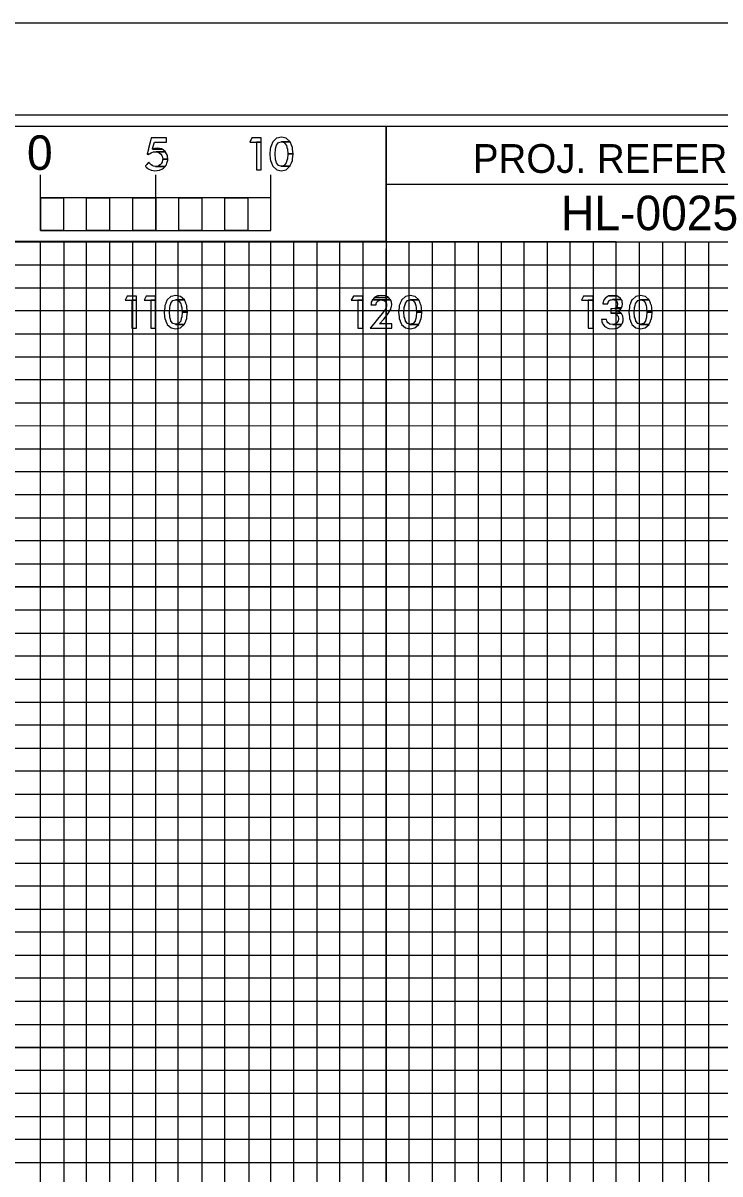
# Model space of a CAD drawing. Extents: x -13 to 323, y -5 to 1431.
# Drawn here: x 264.2 to 294.5, y 604.5 to 654.5 of the extents above; entities that cross this region are included whole.
import ezdxf

# ---------------------------------------------------------------- set-up
doc = ezdxf.new("R2010")
doc.units = 0
for name, color, linetype in [('Prop XS Bar Scale Labels', 7, 'Continuous'), ('Prop XS Offset Labels', 7, 'Continuous'), ('Prop XS Project Number', 7, 'Continuous'), ('Sheet Cross Section CELL', 7, 'Continuous'), ('Sheet Cross Section Grid Major CELL', 7, 'Continuous'), ('Sheet Cross Section Grid Middle CELL', 7, 'Continuous'), ('Sheet Cross Section Grid Minor 1 CELL', 7, 'Continuous'), ('Sheet Cross Section Grid Minor 2 CELL', 7, 'Continuous'), ('Sheet Cross Section Scale CELL', 7, 'Continuous'), ('Sheet Cutting Line CELL', 7, 'Continuous'), ('Sheet DOT Grid CELL', 7, 'Continuous'), ('Sheet Plot Border Inside CELL', 7, 'Continuous'), ('Sheet Plot Border Outside CELL', 7, 'Continuous')]:
    doc.layers.add(name, color=color, linetype=linetype)

msp = doc.modelspace()

# ---------------------------------------------------------------- linework, layer by layer
at = {"layer": 'Prop XS Bar Scale Labels'}
for points in [[(269.63, 648.81), (269.627, 648.798), (269.698, 648.798), (269.711, 648.81), (269.727, 648.824), (269.798, 648.867), (269.83, 648.877), (269.9, 648.899), (270.014, 648.905), (270.422, 648.905), (270.414, 648.92), (270.28, 649.015), (269.858, 649.015), (269.861, 649.028), (269.861, 649.028), (269.866, 649.048), (269.941, 649.326), (270.466, 649.326), (270.466, 649.511), (269.803, 649.511), (269.757, 649.326), (269.689, 649.048), (269.684, 649.028), (269.681, 649.015), (269.658, 648.92), (269.654, 648.905), (269.652, 648.899), (269.647, 648.877), (269.644, 648.867), (269.634, 648.824)], [(274.174, 649.511), (274.085, 649.329), (274.583, 649.329), (274.583, 649.511)], [(275.258, 648.125), (275.457, 648.084), (275.652, 648.125), (275.663, 648.127), (275.828, 648.279), (275.454, 648.279), (275.445, 648.281), (275.44, 648.283), (275.335, 648.312), (275.248, 648.425), (275.248, 648.426), (275.248, 648.426), (275.22, 648.527), (275.22, 648.529), (275.2, 648.602), (275.198, 648.606), (275.181, 648.809), (275.181, 648.811), (275.181, 648.813), (275.198, 649.015), (275.219, 649.092), (275.22, 649.094), (275.246, 649.192), (275.247, 649.195), (275.335, 649.31), (275.448, 649.339), (275.452, 649.34), (275.462, 649.343), (275.832, 649.343), (275.669, 649.492), (275.66, 649.494), (275.46, 649.538), (275.46, 649.538), (275.252, 649.494), (275.25, 649.492), (275.088, 649.343), (275.085, 649.34), (275.084, 649.339), (275.072, 649.31), (275.025, 649.195), (275.024, 649.192), (274.983, 649.094), (274.983, 649.092), (274.975, 649.015), (274.954, 648.813), (274.953, 648.811), (274.954, 648.809), (274.974, 648.606), (274.974, 648.602), (274.982, 648.529), (274.982, 648.527), (275.023, 648.426), (275.024, 648.425), (275.07, 648.312), (275.082, 648.283), (275.082, 648.281), (275.085, 648.279), (275.255, 648.127)], [(269.895, 649.028), (269.858, 649.015), (270.28, 649.015), (270.262, 649.028), (270.164, 649.048), (269.953, 649.048)], [(270.091, 649.062), (269.953, 649.048), (270.164, 649.048), (270.091, 649.062)], [(274.374, 649.329), (274.374, 648.12), (274.583, 648.12), (274.583, 649.329)], [(275.719, 649.015), (275.735, 648.813), (275.962, 648.813), (275.942, 649.015), (275.935, 649.092), (275.934, 649.094), (275.934, 649.094), (275.895, 649.192), (275.895, 649.192), (275.893, 649.195), (275.848, 649.31), (275.847, 649.31), (275.835, 649.339), (275.835, 649.34), (275.832, 649.343), (275.462, 649.343), (275.472, 649.34), (275.475, 649.339), (275.582, 649.31), (275.669, 649.195), (275.672, 649.192), (275.698, 649.094), (275.698, 649.092)], [(269.627, 648.798), (269.685, 648.786), (269.698, 648.798)], [(270.103, 648.288), (269.996, 648.269), (270.408, 648.269), (270.423, 648.288), (270.424, 648.289), (270.425, 648.29), (270.425, 648.29), (270.462, 648.336), (270.471, 648.347), (270.473, 648.353), (270.487, 648.405), (270.502, 648.46), (270.525, 648.544), (270.521, 648.591), (270.308, 648.591), (270.3, 648.544), (270.286, 648.46), (270.25, 648.405), (270.217, 648.353), (270.207, 648.347), (270.19, 648.336), (270.116, 648.29), (270.108, 648.289)], [(270.286, 648.711), (270.308, 648.591), (270.521, 648.591), (270.51, 648.711), (270.51, 648.711), (270.507, 648.751), (270.487, 648.786), (270.481, 648.798), (270.475, 648.81), (270.467, 648.824), (270.443, 648.867), (270.438, 648.877), (270.426, 648.899), (270.422, 648.905), (270.014, 648.905), (270.041, 648.899), (270.132, 648.877), (270.146, 648.867), (270.206, 648.824), (270.227, 648.81), (270.234, 648.798), (270.241, 648.786), (270.262, 648.751)], [(275.465, 648.281), (275.454, 648.279), (275.828, 648.279), (275.831, 648.281), (275.833, 648.283), (275.845, 648.312), (275.892, 648.425), (275.892, 648.426), (275.934, 648.527), (275.935, 648.529), (275.942, 648.602), (275.942, 648.606), (275.962, 648.809), (275.963, 648.811), (275.962, 648.813), (275.735, 648.813), (275.735, 648.811), (275.735, 648.809), (275.719, 648.606), (275.718, 648.602), (275.699, 648.529), (275.698, 648.527), (275.671, 648.426), (275.67, 648.425), (275.582, 648.312), (275.47, 648.283)], [(269.829, 648.103), (269.965, 648.084), (270.163, 648.103), (270.171, 648.107), (270.294, 648.167), (270.294, 648.167), (270.344, 648.191), (270.388, 648.245), (270.408, 648.269), (269.996, 648.269), (269.887, 648.288), (269.885, 648.289), (269.882, 648.29), (269.799, 648.336), (269.789, 648.347), (269.783, 648.353), (269.783, 648.353), (269.733, 648.405), (269.7, 648.455), (269.7, 648.455), (269.655, 648.405), (269.608, 648.353), (269.602, 648.347), (269.593, 648.336), (269.551, 648.29), (269.55, 648.289), (269.551, 648.288), (269.566, 648.269), (269.585, 648.245), (269.649, 648.191), (269.677, 648.167), (269.801, 648.107)]]:
    msp.add_lwpolyline(points, close=True, dxfattribs=at)
at = {"layer": 'Prop XS Offset Labels'}
for points in [[(268.76, 642.641), (268.671, 642.459), (269.17, 642.459), (269.17, 642.641)], [(269.587, 642.641), (269.498, 642.459), (269.997, 642.459), (269.997, 642.641)], [(270.672, 641.255), (270.871, 641.214), (271.066, 641.255), (271.077, 641.257), (271.242, 641.409), (270.868, 641.409), (270.858, 641.411), (270.853, 641.413), (270.749, 641.442), (270.662, 641.555), (270.661, 641.556), (270.661, 641.556), (270.634, 641.657), (270.633, 641.659), (270.613, 641.732), (270.612, 641.736), (270.594, 641.939), (270.594, 641.941), (270.595, 641.943), (270.612, 642.145), (270.633, 642.222), (270.633, 642.224), (270.66, 642.322), (270.661, 642.325), (270.749, 642.44), (270.862, 642.469), (270.865, 642.47), (270.876, 642.473), (271.246, 642.473), (271.082, 642.622), (271.074, 642.624), (270.873, 642.668), (270.873, 642.668), (270.665, 642.624), (270.663, 642.622), (270.502, 642.473), (270.499, 642.47), (270.498, 642.469), (270.486, 642.44), (270.439, 642.325), (270.437, 642.322), (270.397, 642.224), (270.397, 642.222), (270.389, 642.145), (270.367, 641.943), (270.367, 641.941), (270.367, 641.939), (270.387, 641.736), (270.388, 641.732), (270.395, 641.659), (270.396, 641.657), (270.437, 641.556), (270.437, 641.555), (270.483, 641.442), (270.495, 641.413), (270.496, 641.411), (270.499, 641.409), (270.669, 641.257)], [(278.581, 642.641), (278.492, 642.459), (278.99, 642.459), (278.99, 642.641)], [(279.507, 642.583), (279.41, 642.479), (280.197, 642.479), (280.108, 642.583)], [(279.512, 642.585), (279.507, 642.583), (280.108, 642.583), (280.106, 642.585), (279.974, 642.645), (279.958, 642.652), (279.794, 642.668), (279.794, 642.668), (279.685, 642.652), (279.637, 642.645)], [(280.851, 641.255), (281.051, 641.214), (281.245, 641.255), (281.256, 641.257), (281.422, 641.409), (281.048, 641.409), (281.038, 641.411), (281.033, 641.413), (280.928, 641.442), (280.841, 641.555), (280.841, 641.556), (280.841, 641.556), (280.813, 641.657), (280.813, 641.659), (280.793, 641.732), (280.792, 641.736), (280.774, 641.939), (280.774, 641.941), (280.774, 641.943), (280.792, 642.145), (280.812, 642.222), (280.813, 642.224), (280.839, 642.322), (280.84, 642.325), (280.928, 642.44), (281.041, 642.469), (281.045, 642.47), (281.055, 642.473), (281.425, 642.473), (281.262, 642.622), (281.254, 642.624), (281.053, 642.668), (281.053, 642.668), (280.845, 642.624), (280.843, 642.622), (280.681, 642.473), (280.678, 642.47), (280.678, 642.469), (280.665, 642.44), (280.618, 642.325), (280.617, 642.322), (280.577, 642.224), (280.576, 642.222), (280.568, 642.145), (280.547, 641.943), (280.547, 641.941), (280.547, 641.939), (280.567, 641.736), (280.567, 641.732), (280.575, 641.659), (280.575, 641.657), (280.616, 641.556), (280.617, 641.555), (280.663, 641.442), (280.675, 641.413), (280.676, 641.411), (280.679, 641.409), (280.848, 641.257)], [(288.581, 642.641), (288.492, 642.459), (288.99, 642.459), (288.99, 642.641)], [(289.42, 642.315), (289.418, 642.297), (289.626, 642.297), (289.627, 642.315), (289.639, 642.365), (289.64, 642.372), (289.641, 642.373), (289.683, 642.433), (289.688, 642.436), (289.696, 642.44), (289.748, 642.47), (289.785, 642.476), (289.795, 642.478), (289.835, 642.485), (290.217, 642.485), (290.165, 642.561), (290.129, 642.582), (290.128, 642.582), (290.022, 642.644), (289.982, 642.65), (289.69, 642.65), (289.678, 642.644), (289.553, 642.582), (289.536, 642.561), (289.471, 642.485), (289.466, 642.478), (289.465, 642.476), (289.463, 642.47), (289.452, 642.44), (289.45, 642.436), (289.449, 642.433), (289.428, 642.373), (289.427, 642.372), (289.425, 642.365)], [(289.853, 642.668), (289.69, 642.65), (289.982, 642.65)], [(290.851, 641.255), (291.051, 641.214), (291.245, 641.255), (291.256, 641.257), (291.422, 641.409), (291.048, 641.409), (291.038, 641.411), (291.033, 641.413), (290.928, 641.442), (290.841, 641.555), (290.841, 641.556), (290.841, 641.556), (290.813, 641.657), (290.813, 641.659), (290.793, 641.732), (290.792, 641.736), (290.774, 641.939), (290.774, 641.941), (290.774, 641.943), (290.792, 642.145), (290.812, 642.222), (290.813, 642.224), (290.839, 642.322), (290.84, 642.325), (290.928, 642.44), (291.041, 642.469), (291.045, 642.47), (291.055, 642.473), (291.425, 642.473), (291.262, 642.622), (291.254, 642.624), (291.053, 642.668), (291.053, 642.668), (290.845, 642.624), (290.843, 642.622), (290.681, 642.473), (290.678, 642.47), (290.678, 642.469), (290.665, 642.44), (290.618, 642.325), (290.617, 642.322), (290.577, 642.224), (290.576, 642.222), (290.568, 642.145), (290.547, 641.943), (290.547, 641.941), (290.547, 641.939), (290.567, 641.736), (290.567, 641.732), (290.575, 641.659), (290.575, 641.657), (290.616, 641.556), (290.617, 641.555), (290.663, 641.442), (290.675, 641.413), (290.676, 641.411), (290.679, 641.409), (290.848, 641.257)], [(268.961, 642.459), (268.961, 641.25), (269.17, 641.25), (269.17, 642.459)], [(269.788, 642.459), (269.788, 641.25), (269.997, 641.25), (269.997, 642.459)], [(271.132, 642.145), (271.149, 641.943), (271.376, 641.943), (271.356, 642.145), (271.349, 642.222), (271.348, 642.224), (271.348, 642.224), (271.308, 642.322), (271.308, 642.322), (271.307, 642.325), (271.261, 642.44), (271.261, 642.44), (271.249, 642.469), (271.249, 642.47), (271.246, 642.473), (270.876, 642.473), (270.885, 642.47), (270.889, 642.469), (270.995, 642.44), (271.083, 642.325), (271.085, 642.322), (271.111, 642.224), (271.112, 642.222)], [(278.781, 642.459), (278.781, 641.25), (278.99, 641.25), (278.99, 642.459)], [(279.465, 641.432), (279.313, 641.25), (280.253, 641.25), (280.253, 641.432), (279.719, 641.432), (279.898, 641.638), (280.095, 641.879), (280.097, 641.881), (280.208, 642.069), (280.208, 642.069), (280.211, 642.074), (280.235, 642.193), (280.247, 642.254), (280.252, 642.279), (280.25, 642.29), (280.249, 642.293), (280.236, 642.354), (280.235, 642.36), (280.233, 642.37), (280.222, 642.421), (280.222, 642.421), (280.219, 642.435), (280.213, 642.461), (280.211, 642.464), (280.207, 642.468), (279.839, 642.468), (279.85, 642.464), (279.858, 642.461), (279.933, 642.435), (279.946, 642.421), (279.996, 642.37), (280, 642.36), (280.002, 642.354), (280.022, 642.293), (280.022, 642.29), (280.022, 642.279), (280.022, 642.254), (280.021, 642.193), (279.973, 642.074), (279.972, 642.069), (279.839, 641.881), (279.838, 641.879), (279.637, 641.638)], [(279.349, 642.279), (279.347, 642.254), (279.567, 642.254), (279.569, 642.279), (279.57, 642.29), (279.571, 642.293), (279.593, 642.354), (279.598, 642.36), (279.606, 642.37), (279.645, 642.421), (279.673, 642.435), (279.725, 642.461), (279.73, 642.464), (279.839, 642.468), (280.207, 642.468), (280.197, 642.479), (279.41, 642.479), (279.405, 642.468), (279.403, 642.464), (279.402, 642.461), (279.39, 642.435), (279.384, 642.421), (279.361, 642.37), (279.357, 642.36), (279.356, 642.354), (279.35, 642.293), (279.35, 642.29)], [(281.312, 642.145), (281.328, 641.943), (281.555, 641.943), (281.536, 642.145), (281.528, 642.222), (281.528, 642.224), (281.527, 642.224), (281.488, 642.322), (281.488, 642.322), (281.487, 642.325), (281.441, 642.44), (281.44, 642.44), (281.429, 642.469), (281.428, 642.47), (281.425, 642.473), (281.055, 642.473), (281.065, 642.47), (281.068, 642.469), (281.175, 642.44), (281.262, 642.325), (281.265, 642.322), (281.291, 642.224), (281.291, 642.222)], [(288.781, 642.459), (288.781, 641.25), (288.99, 641.25), (288.99, 642.459)], [(289.765, 641.956), (289.765, 641.9), (290.194, 641.9), (290.119, 641.956), (290.029, 641.983), (290.095, 642), (290.181, 642.053), (290.2, 642.084), (290.201, 642.085), (290.207, 642.095), (289.915, 642.095), (289.83, 642.085), (289.765, 642.084), (289.765, 642.053), (289.765, 642), (289.765, 641.983)], [(290.007, 642.155), (289.988, 642.131), (290.23, 642.131), (290.246, 642.155), (290.254, 642.201), (290.271, 642.289), (290.272, 642.295), (290.272, 642.297), (290.269, 642.315), (290.26, 642.365), (290.259, 642.372), (290.259, 642.373), (290.259, 642.373), (290.249, 642.433), (290.248, 642.436), (290.248, 642.44), (290.227, 642.47), (290.223, 642.476), (290.222, 642.478), (290.217, 642.485), (289.835, 642.485), (289.901, 642.478), (289.919, 642.476), (289.931, 642.47), (289.986, 642.44), (289.995, 642.436), (289.997, 642.433), (290.04, 642.373), (290.04, 642.372), (290.042, 642.365), (290.051, 642.315), (290.054, 642.297), (290.055, 642.295), (290.056, 642.289), (290.041, 642.201)], [(289.988, 642.131), (289.915, 642.095), (290.207, 642.095), (290.23, 642.131)], [(291.312, 642.145), (291.328, 641.943), (291.555, 641.943), (291.536, 642.145), (291.528, 642.222), (291.528, 642.224), (291.527, 642.224), (291.488, 642.322), (291.488, 642.322), (291.487, 642.325), (291.441, 642.44), (291.44, 642.44), (291.429, 642.469), (291.428, 642.47), (291.425, 642.473), (291.055, 642.473), (291.065, 642.47), (291.068, 642.469), (291.175, 642.44), (291.262, 642.325), (291.265, 642.322), (291.291, 642.224), (291.291, 642.222)], [(270.878, 641.411), (270.868, 641.409), (271.242, 641.409), (271.245, 641.411), (271.247, 641.413), (271.259, 641.442), (271.305, 641.555), (271.306, 641.556), (271.348, 641.657), (271.348, 641.659), (271.355, 641.732), (271.356, 641.736), (271.376, 641.939), (271.376, 641.941), (271.376, 641.943), (271.149, 641.943), (271.149, 641.941), (271.148, 641.939), (271.132, 641.736), (271.132, 641.732), (271.112, 641.659), (271.112, 641.657), (271.085, 641.556), (271.084, 641.555), (270.995, 641.442), (270.883, 641.413)], [(281.058, 641.411), (281.048, 641.409), (281.422, 641.409), (281.425, 641.411), (281.426, 641.413), (281.438, 641.442), (281.485, 641.555), (281.485, 641.556), (281.527, 641.657), (281.528, 641.659), (281.535, 641.732), (281.535, 641.736), (281.555, 641.939), (281.556, 641.941), (281.555, 641.943), (281.328, 641.943), (281.328, 641.941), (281.328, 641.939), (281.312, 641.736), (281.312, 641.732), (281.292, 641.659), (281.291, 641.657), (281.264, 641.556), (281.263, 641.555), (281.175, 641.442), (281.063, 641.413)], [(289.677, 641.229), (289.854, 641.214), (289.936, 641.229), (290.042, 641.248), (290.123, 641.297), (290.187, 641.336), (290.228, 641.399), (290.229, 641.401), (289.849, 641.401), (289.72, 641.416), (289.711, 641.423), (289.639, 641.471), (289.628, 641.479), (289.626, 641.482), (289.608, 641.516), (289.584, 641.562), (289.584, 641.567), (289.58, 641.62), (289.58, 641.625), (289.361, 641.625), (289.362, 641.62), (289.369, 641.567), (289.37, 641.562), (289.377, 641.516), (289.391, 641.482), (289.392, 641.479), (289.395, 641.471), (289.415, 641.423), (289.418, 641.416), (289.425, 641.401), (289.426, 641.399), (289.49, 641.336), (289.53, 641.297), (289.635, 641.248)], [(289.925, 641.416), (289.849, 641.401), (290.229, 641.401), (290.239, 641.416), (290.243, 641.423), (290.243, 641.423), (290.275, 641.471), (290.277, 641.479), (290.277, 641.482), (290.283, 641.516), (290.292, 641.562), (290.293, 641.567), (290.303, 641.62), (290.297, 641.662), (290.285, 641.751), (290.283, 641.763), (290.25, 641.826), (290.223, 641.877), (290.222, 641.88), (290.197, 641.898), (290.194, 641.9), (289.81, 641.9), (289.877, 641.898), (289.951, 641.88), (289.963, 641.877), (290.033, 641.826), (290.07, 641.763), (290.077, 641.751), (290.092, 641.662), (290.088, 641.62), (290.082, 641.567), (290.08, 641.562), (290.057, 641.516), (290.039, 641.482), (290.035, 641.479), (290.025, 641.471), (289.957, 641.423)], [(291.058, 641.411), (291.048, 641.409), (291.422, 641.409), (291.425, 641.411), (291.426, 641.413), (291.438, 641.442), (291.485, 641.555), (291.485, 641.556), (291.527, 641.657), (291.528, 641.659), (291.535, 641.732), (291.535, 641.736), (291.555, 641.939), (291.556, 641.941), (291.555, 641.943), (291.328, 641.943), (291.328, 641.941), (291.328, 641.939), (291.312, 641.736), (291.312, 641.732), (291.292, 641.659), (291.291, 641.657), (291.264, 641.556), (291.263, 641.555), (291.175, 641.442), (291.063, 641.413)]]:
    msp.add_lwpolyline(points, close=True, dxfattribs=at)
at = {"layer": 'Sheet Cross Section CELL'}
for p, q in [((280, 647.5), (280, 645)), ((320, 647.49), (280, 647.49)), ((280, 645), (320, 645))]:
    msp.add_line(p, q, dxfattribs=at)
for points in [[(320, 650), (0, 650), (0, 440), (320, 440)], [(280, 650), (260, 650), (260, 645.03), (280, 645.03)], [(320, 650), (280, 650), (280, 645), (320, 645)]]:
    msp.add_lwpolyline(points, close=True, dxfattribs=at)
at = {"layer": 'Sheet Cross Section Grid Major CELL'}
for p, q in [((270, 440), (270, 645)), ((290, 645), (280, 645)), ((280, 645), (280, 440)), ((290, 440), (290, 645))]:
    msp.add_line(p, q, dxfattribs=at)
for points in [[(0, 640), (320, 640), (320, 630), (0, 630)], [(0, 620), (320, 620), (320, 610), (0, 610)]]:
    msp.add_lwpolyline(points, dxfattribs=at)
at = {"layer": 'Sheet Cross Section Grid Middle CELL'}
for points in [[(255, 440), (255, 650), (259.93, 650), (260, 650), (260, 645), (264.99, 645), (264.99, 440)], [(0, 645), (275, 645)], [(275, 440), (275, 645), (285, 645), (285, 440)], [(0, 625), (320, 625), (320, 635), (0, 635)], [(0, 605), (320, 605), (320, 615), (0, 615)]]:
    msp.add_lwpolyline(points, dxfattribs=at)
at = {"layer": 'Sheet Cross Section Grid Minor 1 CELL'}
msp.add_line((0, 644), (320, 644), dxfattribs=at)
for points in [[(0, 643), (270, 643), (320, 643), (320, 642), (0, 642)], [(0, 641), (320, 641), (320, 639), (0, 639)], [(0, 638), (320, 638), (320, 637), (0, 636.98)], [(0, 636), (320, 636), (320, 634), (0, 634)], [(0, 633), (320, 633), (320, 632), (0, 632)], [(0, 631), (320, 631), (320, 629), (0, 629)], [(0, 628), (320, 628), (320, 627), (0, 627)], [(0, 626), (320, 626), (320, 624), (0, 624)], [(0, 623), (320, 623), (320, 622), (0, 622)], [(0, 621), (320, 621), (320, 619), (0, 619)], [(0, 618), (320, 618), (320, 617), (0, 617)], [(0, 616), (320, 616), (320, 613.95), (320, 613), (320, 612), (0, 612)], [(0, 614), (320, 614), (320, 613), (0, 613)], [(0, 611), (320, 611), (320, 609), (0, 609.03)], [(0, 609.03), (320, 609), (320, 608), (0, 608)], [(0, 607), (320, 607), (320, 606), (0, 606)]]:
    msp.add_lwpolyline(points, dxfattribs=at)
at = {"layer": 'Sheet Cross Section Grid Minor 2 CELL'}
for p, q in [((267, 645), (266.01, 645)), ((266.01, 645), (266.01, 440)), ((267, 440), (267, 645)), ((269, 645), (268, 645)), ((268, 645), (268, 440)), ((269, 440), (269, 645))]:
    msp.add_line(p, q, dxfattribs=at)
for points in [[(270, 440), (270.98, 440), (270.98, 645), (272, 645), (272, 440)], [(272, 440), (273, 440), (273, 645), (274.05, 645), (274.05, 440)], [(275, 440), (276, 440), (276, 645), (277, 645), (277, 440)], [(277, 440), (278, 440), (278, 645), (279, 645), (279, 440)], [(280, 440), (281, 440), (281, 645), (282, 645), (282, 440)], [(282, 440), (283, 440), (283, 645), (284, 645), (284, 440)], [(285, 440), (286, 440), (286, 645), (287, 645), (287, 440)], [(287, 440), (288, 440), (288, 645), (289, 645), (289, 440)], [(290, 440), (291, 440), (291, 645), (292, 645), (292, 440)], [(292, 440), (293, 440), (293, 645), (294, 645), (294, 440)]]:
    msp.add_lwpolyline(points, dxfattribs=at)
at = {"layer": 'Sheet Cross Section Scale CELL'}
for p, q in [((265, 645.49), (265, 647.9)), ((265, 646.9), (265, 647.9)), ((270, 645.49), (270, 647.9)), ((275, 645.49), (275, 647.9)), ((275, 646.9), (275, 647.9))]:
    msp.add_line(p, q, dxfattribs=at)
for points in [[(275, 646.9), (265, 646.9), (265, 645.49), (275, 645.49)], [(265, 646.9), (266, 646.9), (266, 645.49), (265, 645.49)], [(267, 646.9), (268, 646.9), (268, 645.49), (267, 645.49)], [(269, 646.9), (270, 646.9), (270, 645.49), (269, 645.49)], [(271, 646.9), (272, 646.9), (272, 645.49), (271, 645.49)], [(273, 646.9), (274, 646.9), (274, 645.49), (273, 645.49)]]:
    msp.add_lwpolyline(points, close=True, dxfattribs=at)
at = {"layer": 'Sheet Cutting Line CELL'}
msp.add_line((323.3, 654.5), (-13.4, 654.5), dxfattribs=at)
at = {"layer": 'Sheet DOT Grid CELL'}
for p, q in [((270, 440), (270, 644.687)), ((280, 440), (280, 644.687)), ((290, 440), (290, 644.687)), ((0, 640), (320, 640)), ((0, 630), (320, 630)), ((0, 620), (320, 620)), ((0, 610), (320, 610))]:
    msp.add_line(p, q, dxfattribs=at)
at = {"layer": 'Sheet Plot Border Inside CELL'}
msp.add_lwpolyline([(-10.8, 439.5), (322.4, 439.5), (322.4, 650.5), (-10.8, 650.5)], close=True, dxfattribs=at)
at = {"layer": 'Sheet Plot Border Outside CELL'}
msp.add_lwpolyline([(-13.4, 435.5), (323.3, 435.5), (323.3, 654.5), (-13.4, 654.5)], close=True, dxfattribs=at)

# ---------------------------------------------------------------- texts
at = {"layer": 'Prop XS Project Number'}
msp.add_text('HL-0025', height=1.5, dxfattribs=at).set_placement((287.598, 645.5))
at = {"layer": 'Sheet Cross Section CELL'}
msp.add_text('PROJ. REFERENCE NO.', height=1.24998, dxfattribs=at).set_placement((283.77, 647.99))
at = {"layer": 'Sheet Cross Section Scale CELL'}
msp.add_text('0', height=1.5, dxfattribs=at).set_placement((264.41, 648.12))

doc.saveas('drawing.dxf')
